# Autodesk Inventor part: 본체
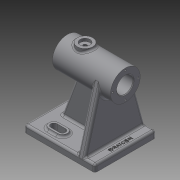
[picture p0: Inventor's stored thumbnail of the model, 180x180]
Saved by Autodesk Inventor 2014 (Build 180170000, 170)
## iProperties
Created: 2019-10
Part Number: 본체
Material: Generic
Document SubType Name: Modeling
Designer: kh
Density: 1 g/cm^3
Appearance: Default
Mass: 217.202 g
Surface Area: 540.35 cm^2
Volume: 217.202 cm^3
Author: kh
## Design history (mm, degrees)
sketch "Sketch1"
  geometry: L1 (-50, -43)-(50, -43); L2 (50, -43)-(50, 43); L3 (50, 43)-(-50, 43); L4 (-50, 43)-(-50, -43); L5 (-50, -43)-(50, 43); L6 (50, -43)-(-50, 43); 1 further point
  constraints: 12 end point, 2 midpoint, 2 parallel, 1 horizontal, 1 perpendicular
  dimensions: "d0" = 100 distance of L2.end L3.end; "d1" = 86 distance of L1.end L2.end
extrude "Extrusion1" new body sketch "Sketch1" distance "d2" = 10; taper "d3" = 0 deg
sketch "Sketch2"
  geometry: L1 (50, 0)-(-50, 0) reference; L2 (50, 107)-(50, 86); L3 (50, 86)-(-32, 86); L4 (-32, 86)-(-32, 107); L5 (-32, 107)-(50, 107); 2 further points
  constraints: 8 end point, 2 parallel, 2 perpendicular, 1 midpoint, 1 vertical alignment
  dimensions: "d9" = 42 diameter of L5 L3; "d10" = 86 distance from line of L2.end L1; "d11" = 82 distance between parallel lines of L4 L2
revolve "Revolution2" sketch "Sketch2" stored, may be unused: angle "d12" = 90 deg
sketch "Sketch3"
  geometry: L1 (50, 65)-(50, 107) reference; L2 (-32, 65)-(-32, 107) reference; L3 (-32, 86)-(50, 86); L4 (-32, 86)-(30, 86); L5 (30, 86)-(30, 100.5); L6 (30, 100.5)-(-32, 100.5); L7 (-32, 100.5)-(-32, 86); L8 (30, 86)-(50, 86); L9 (50, 86)-(50, 97.5); L10 (50, 97.5)-(30, 97.5); L11 (30, 97.5)-(30, 86); 1 further point
  constraints: 18 end point, 4 parallel, 2 horizontal, 2 midpoint, 2 perpendicular, 1 point on line
  dimensions: "d13" = 29 diameter of L6 L3; "d14" = 23 diameter of L10 L3; "d15" = 62 distance between parallel lines of L5 L2
revolve "Revolution3" sketch "Sketch3" stored, may be unused: angle "d16" = 90 deg
workplane "Work Plane1"
fillet "Fillet1" dims "d35" = 3
fillet "Fillet2" dims "d36" = 3
workplane "Work Plane3"
sketch "Sketch16"
  geometry: L1 (5.48, 20.272)-(-78.217, 42.896); L2 (5.48, -20.272)-(-78.217, -42.896); L3 (-76, 40)-(-76, -40); A1 r 3 centre (-79, -40) between (-79, -43) and (-76, -40) reference; A2 r 21 centre (0, 0) between (5.48, 20.272) and (5.48, -20.272) reference; A3 r 21 centre (0, 0) between (5.48, 20.272) and (5.48, -20.272); A4 r 3 centre (-79, 40) between (-76, 40) and (-79, 43) reference; A5 r 3 centre (-79, 40) between (-76, 40) and (-78.217, 42.896); A6 r 3 centre (-79, -40) between (-78.217, -42.896) and (-76, -40); 1 further point
  constraints: 10 point on circle, 7 tangent, 6 end point, 3 centre point, 2 concentric, 1 vertical
sketch "Sketch17"
  geometry: L1 (50, -40)-(50, 40) reference; L2 (32, 21)-(32, -21) reference; C1 r 11 at (7, 0); 2 further points
  constraints: 1 centre point, 1 horizontal alignment, 1 midpoint
  dimensions: "d41" = 22 diameter of C1; "d43" = 25 distance from line of C1.centre L2
extrude "Extrusion4" join sketch "Sketch17" stored distance "d44" = 10; taper "d45" = 0 deg
hole "Hole2" diameter "d48" = 4.917; stored, may be unused: countersink angle "d52" = 90 deg, drill point angle "d54" = 118 deg; dims "d46" = 10, "d47" = 10, "d49" = 6, "d50" = 14, "d51" = 4, "d53" = 8
sketch "Sketch21"
  geometry: L1 (-47, 10)-(47, 10) reference; L2 (-32, 65)-(50, 65) reference; L3 (-35, 10)-(-14.982, 65); A1 r 3 centre (-47, 7) between (-47, 10) and (-50, 7) reference; 1 further point
  constraints: 2 end point, 2 point on line
  dimensions: "d62" = 70 deg angle of L1 L3; "d63" = 15 horizontal distance of A1.end L3.start
sketch "Sketch22"
  geometry: C1 r 11.5 at (0, 0) reference; A1 r 18 centre (0, 0) between (18, 0) and (0, 18); 3 further points
  constraints: 4 point on circle, 1 centre point, 1 coincident
  dimensions: "d70" = 36 diameter of A1
hole "Hole3" sketch "Sketch22" at (18, 0), (0, 18), (-18, 0), (0, -18) diameter "d71" = 2.459; stored, may be unused: countersink angle "d75" = 90 deg, drill point angle "d77" = 118 deg; dims "d72" = 8, "d73" = 14, "d74" = 4, "d76" = 10
sketch "Sketch23"
  geometry: C1 r 14.5 at (0, 0) reference; A1 r 18 centre (0, 0) between (-18, 0) and (0, -18); 3 further points
  constraints: 4 point on circle, 1 centre point, 1 coincident
  dimensions: "d78" = 36 diameter of A1
hole "Hole4" sketch "Sketch23" at (-18, 0), (0, -18), (18, 0), (0, 18) diameter "d79" = 2.459; stored, may be unused: countersink angle "d83" = 90 deg, drill point angle "d85" = 118 deg; dims "d80" = 8, "d81" = 14, "d82" = 4, "d84" = 10
chamfer "Chamfer1" distance "d86" = 1; stored, may be unused: second distance "d87" = 2, angle "d88" = 45 deg
fillet "Fillet3" dims "d89" = 3
extrude "Extrusion5" join sketch "Sketch16" distance "d93" = 10; taper "d94" = 0 deg
feature "Rib2" dims "d95" = 1, "d96" = 10, "d97" = 0, "d98" = 0, "d99" = 1, "d100" = 1
fillet "Fillet7" dims "d101" = 3
fillet "Fillet8" dims "d102" = 3
sketch "Sketch24"
  geometry: L1 (24, -27)-(12, -27); L2 (24, -20)-(12, -20); L3 (12, -34)-(24, -34); L4 (50, -40)-(50, 40) reference; A1 r 7 centre (24, -27) between (24, -34) and (24, -20); A2 r 7 centre (12, -27) between (12, -20) and (12, -34); 2 further points
  constraints: 8 end point, 4 point on circle, 4 tangent, 2 centre point, 1 horizontal, 1 midpoint, 1 parallel
  dimensions: "d103" = 27 vertical distance of point (18, -27) point (0, 0); "d104" = 14 distance between parallel lines of L3 L2; "d118" = 12 distance of L1.start L1.end; "d119" = 26 distance from line of L1.start L4
extrude "Extrusion6" join sketch "Sketch24" distance "d107" = 3; taper "d108" = 0 deg
sketch "Sketch25"
  geometry: L1 (24, -34)-(12, -34) reference; L2 (24, -34)-(12, -34) reference; L3 (12, -20)-(24, -20) reference; L4 (-22, 8)-(-22, 38.378) reference; L5 (30.716, 8)-(-22, 8) reference; L6 (37.101, -2)-(37.101, 2) reference; L7 (-22, -8)-(30.716, -8) reference; L8 (-22, -38.378)-(-22, -8) reference; L9 (47, -40)-(-22.208, -40) reference; L10 (47, 40)-(47, -40) reference; L11 (-22.208, 40)-(47, 40) reference; L12 (24, -27)-(12, -27); L13 (24, -22.5)-(12, -22.5); L14 (12, -31.5)-(24, -31.5); A1 r 7 centre (24, -27) between (24, -34) and (24, -20) reference; A2 r 7 centre (12, -27) between (12, -20) and (12, -34) reference; A3 r 4.5 centre (24, -27) between (24, -31.5) and (24, -22.5); A4 r 4.5 centre (12, -27) between (12, -22.5) and (12, -31.5); 6 further points; 4 other entities
  constraints: 8 end point, 4 point on circle, 4 tangent, 2 centre point, 2 parallel, 1 midpoint, 4 other
  dimensions: "d109" = 9 distance between parallel lines of L14 L13
extrude "Extrusion7" cut sketch "Sketch25" stored distance "d110" = 10; taper "d111" = 0 deg
fillet "Fillet9" dims "d112" = 3
mirror "Mirror1"
workplane "Work Plane4"
sketch "Sketch26"
  geometry: L1 (-40.598, 16.592)-(-40.598, -16.592); L2 (-40.598, -16.592)-(-45.402, -16.592); L3 (-45.402, -16.592)-(-45.402, 16.592); L4 (-45.402, 16.592)-(-40.598, 16.592); L5 (-40.598, 16.592)-(-45.402, -16.592); L6 (-40.598, -16.592)-(-45.402, 16.592); L7 (47, 43)-(-47, 43) reference; L8 (-50, 40)-(-50, -40) reference; 2 further points
  constraints: 4 end point, 1 midpoint, 2 other
  dimensions: "d114" = 43 distance from line of point (-43, 0) L7; "d115" = 7 distance from line of L8 point (-43, 0)
emboss "Emboss1" sketch "Sketch26" dims "d0" = 100, "d1" = 86, "d116" = 0.5, "d117" = 0
fillet "Fillet10" dims "d120" = 3
body "Solid1"
node "Projected Loop1"
node "Projected Loop7"
other parameters: "d38" = -15, "d113" = 6.25
